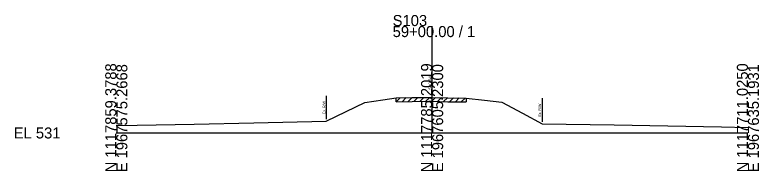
# Model space of a CAD drawing. Extents: x -26 to 163, y -10 to 24018.
# Drawn here: x -25.7 to 162.8, y 8490.3 to 8530 of the extents above; entities that cross this region are included whole.
import ezdxf

# ---------------------------------------------------------------- set-up
doc = ezdxf.new("R2010")
doc.units = 0
for name, color, linetype in [('RD_GPK_XS_Cell', 7, 'Continuous'), ('RD_XS_ExGround', 7, 'Continuous'), ('RD_XS_ExPaveRet', 7, 'Continuous'), ('RD_XS_ExRW', 7, 'Continuous'), ('RD_XS_TX_Elev_EX', 7, 'Continuous')]:
    doc.layers.add(name, color=color, linetype=linetype)

msp = doc.modelspace()

# ---------------------------------------------------------------- linework, layer by layer
at = {"layer": 'RD_GPK_XS_Cell'}
for p, q in [((80, 8500), (80, 8527.15)), ((0, 8500), (80, 8500)), ((80, 8500), (160, 8500))]:
    msp.add_line(p, q, dxfattribs=at)
at = {"layer": 'RD_XS_ExGround'}
msp.add_lwpolyline([(0, 8501.9), (0.46, 8501.89), (19.76, 8502.22), (34.88, 8502.56), (53.2, 8502.97), (58.26, 8505.45), (62.92, 8507.73), (67.49, 8508.44), (70.9, 8508.93), (74.95, 8508.99), (79.28, 8509.05), (80, 8509.04), (83.95, 8508.95), (88.61, 8508.87), (93.26, 8508.31), (97.63, 8507.85), (102.89, 8505), (107.85, 8502.31), (126.16, 8502.09), (153.28, 8501.54), (160, 8501.42)], dxfattribs=at)
at = {"layer": 'RD_XS_ExPaveRet'}
for p, q in [((70.9, 8507.93), (71.92, 8508.94)), ((70.9, 8507.93), (70.9, 8508.93)), ((72.4, 8507.95), (73.42, 8508.97)), ((73.9, 8507.97), (74.92, 8508.99)), ((75.4, 8507.99), (76.42, 8509.01)), ((76.9, 8508.02), (77.92, 8509.03)), ((78.4, 8508.04), (79.41, 8509.05)), ((79.9, 8508.04), (80.88, 8509.02)), ((81.4, 8508), (82.38, 8508.98)), ((82.9, 8507.97), (83.88, 8508.95)), ((84.4, 8507.94), (85.39, 8508.92)), ((85.9, 8507.91), (86.89, 8508.9)), ((87.4, 8507.89), (88.39, 8508.87)), ((88.61, 8508.87), (88.61, 8507.87)), ((70.9, 8507.93), (74.95, 8507.99)), ((74.95, 8507.99), (79.28, 8508.05)), ((79.28, 8508.05), (80, 8508.04)), ((80, 8508.04), (83.95, 8507.95)), ((83.95, 8507.95), (88.61, 8507.87))]:
    msp.add_line(p, q, dxfattribs=at)
at = {"layer": 'RD_XS_ExRW'}
for p, q in [((53.2, 8509.47), (53.2, 8503.47)), ((107.85, 8508.81), (107.85, 8502.81))]:
    msp.add_line(p, q, dxfattribs=at)

# ---------------------------------------------------------------- texts
at = {"layer": 'RD_GPK_XS_Cell'}
for s, p in [('S103', (70, 8527.15)), ('59+00.00 / 1', (70, 8524.35)), ('EL 531', (-26, 8498.6))]:
    msp.add_text(s, height=2.8, dxfattribs=at).set_placement(p)
for s, p in [('N 1117859.3788', (0, 8490)), ('E 1967575.2668', (2.8, 8490)), ('N 1117785.2019', (80, 8490)), ('E 1967605.2300', (82.8, 8490)), ('N 1117711.0250', (160, 8490)), ('E 1967635.1931', (162.8, 8490))]:
    msp.add_text(s, height=2.8, rotation=90, dxfattribs=at).set_placement(p)
at = {"layer": 'RD_XS_ExRW'}
for p in [(52.95, 8504.81), (107.6, 8504.15)]:
    msp.add_text('Ex. R/W ', height=0.65, rotation=90, dxfattribs=at).set_placement(p)
at = {"layer": 'RD_XS_TX_Elev_EX'}
msp.add_text('540.04', height=0.8, rotation=90, dxfattribs=at).set_placement((79.9, 8511.04))

doc.saveas('drawing.dxf')
